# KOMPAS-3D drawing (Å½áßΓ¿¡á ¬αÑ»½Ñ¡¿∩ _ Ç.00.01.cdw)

Views: Справа 1, Справа, Проекционный вид 2, Изометрия XYZ 3, Изометрия XYZ
Referenced files in C:\Users\s.slezkin\Desktop\Раскатчик арок 2\: Пластина крепления _ А.00.01.m3d, Пластина крепления _ А.00.01.cdw
Referenced files: graphic.tdp
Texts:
  Пластина крепления
  http://vk.com/sergey_krd
  Участки приварки
  пластин крепления штанги
  1. PCD от 98 до 120 мм.
  Лит-Масса-Масштаб
  Материал-Предприятие
  Title Specification
  Body Specification ( left align )
  Body Specificaton ( centered )
  Поз.
  Кол.
  Приме-
  чание
  Таблица спецификации
  Пластина
  крепления
Dimensions and other numbers on the sheet: 4,5; 3; 11; 75; 27,5; 33,99; 7; 5; 140; 9; 1; 1:1; 0,33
